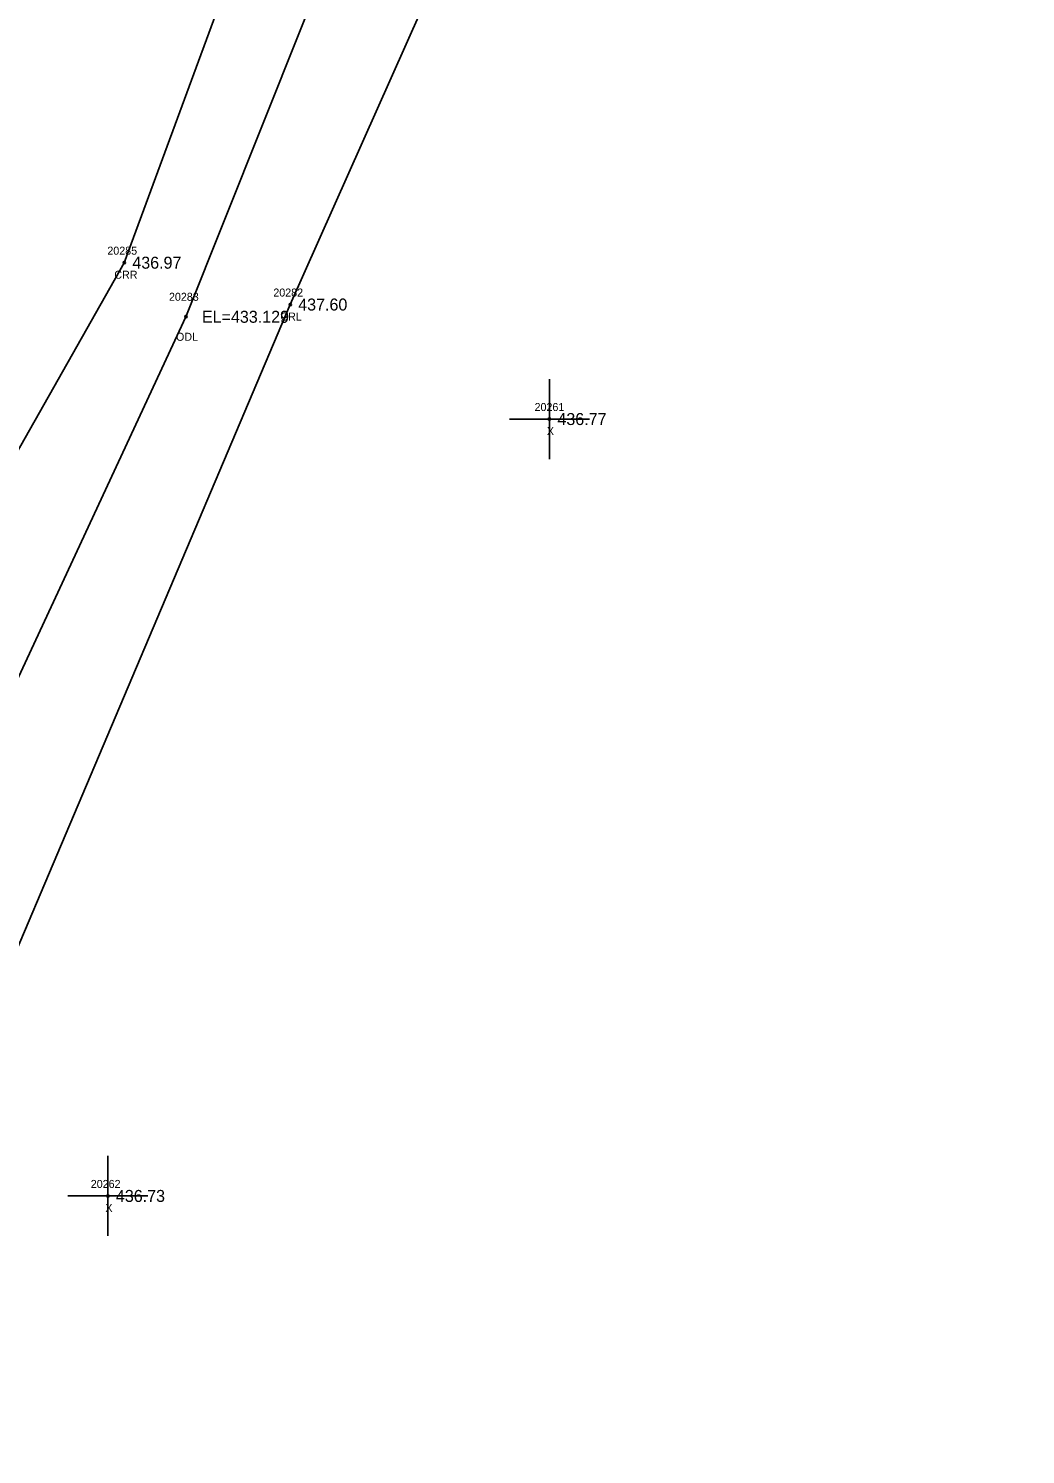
# Model space of a CAD drawing. Extents: x 1797709 to 1799052, y 896018 to 896955.
# Drawn here: x 1798539.1 to 1798663.7, y 896576.7 to 896754.9 of the extents above; entities that cross this region are included whole.
import ezdxf

# ---------------------------------------------------------------- set-up
doc = ezdxf.new("R2010")
doc.units = 0
for name, color, linetype in [('RD_EX_H2O', 7, 'Continuous'), ('RD_EX_H2O_txCode', 7, 'Continuous'), ('RD_EX_Misc', 7, 'Continuous'), ('RD_EX_Misc_txCode', 7, 'Continuous'), ('RD_EX_TX_H2O_ELEV', 7, 'Continuous'), ('RD_EX_TX_Misc_ELEV', 7, 'Continuous'), ('RD_SMD_Locator', 7, 'Continuous')]:
    doc.layers.add(name, color=color, linetype=linetype)

msp = doc.modelspace()

# ---------------------------------------------------------------- linework, layer by layer
at = {"layer": 'RD_EX_H2O'}
for points in [[(1798652.43, 896917.58), (1798601.94, 896827.15), (1798558.78, 896718.92), (1798516.66, 896628.32), (1798463.08, 896540.21), (1798439.21, 896521.86), (1798389.85, 896497.35), (1798369.72, 896471.55), (1798343.52, 896433.35), (1798291.39, 896374.31), (1798235.39, 896326.89), (1798184.99, 896269.63), (1798095.18, 896198.01), (1798023.89, 896139.85)], [(1798638.77, 896915.93), (1798589.91, 896831.16), (1798551.08, 896725.68), (1798509.78, 896652.75)], [(1798663.68, 896911.94), (1798617.01, 896821.94), (1798571.81, 896720.45), (1798529.2, 896619.95), (1798471.21, 896532.04), (1798459.45, 896520.86)]]:
    msp.add_lwpolyline(points, dxfattribs=at)
at = {"layer": 'RD_EX_Misc'}
for p, q in [((1798604.2, 896701.14), (1798604.2, 896711.14)), ((1798599.2, 896706.14), (1798609.2, 896706.14)), ((1798549.03, 896604.04), (1798549.03, 896614.04)), ((1798544.03, 896609.04), (1798554.03, 896609.04))]:
    msp.add_line(p, q, dxfattribs=at)
at = {"layer": 'RD_SMD_Locator'}
for centre in [(1798551.08, 896725.68), (1798571.81, 896720.45), (1798558.78, 896718.92), (1798604.2, 896706.14), (1798549.03, 896609.04)]:
    msp.add_circle(centre, 0.15, dxfattribs=at)

# ---------------------------------------------------------------- texts
at = {"layer": 'RD_EX_H2O_txCode'}
for s, p in [('20285', (1798548.96, 896726.68)), ('CRR', (1798549.83, 896723.68)), ('20283', (1798556.66, 896720.92)), ('20282', (1798569.7, 896721.45)), ('CRL', (1798570.58, 896718.45)), ('ODL', (1798557.54, 896715.92))]:
    msp.add_text(s, height=1, dxfattribs=at).set_placement(p)
at = {"layer": 'RD_EX_Misc_txCode'}
for s, p in [('20261', (1798602.34, 896707.14)), ('X', (1798603.88, 896704.14)), ('20262', (1798546.89, 896610.04)), ('X', (1798548.71, 896607.04))]:
    msp.add_text(s, height=1, dxfattribs=at).set_placement(p)
at = {"layer": 'RD_EX_TX_H2O_ELEV'}
for s, p in [('436.97', (1798552.08, 896724.93)), ('437.60', (1798572.81, 896719.7)), ('EL=433.129', (1798560.78, 896718.17))]:
    msp.add_text(s, height=1.5, dxfattribs=at).set_placement(p)
at = {"layer": 'RD_EX_TX_Misc_ELEV'}
for s, p in [('436.77', (1798605.2, 896705.39)), ('436.73', (1798550.03, 896608.29))]:
    msp.add_text(s, height=1.5, dxfattribs=at).set_placement(p)

doc.saveas('drawing.dxf')
